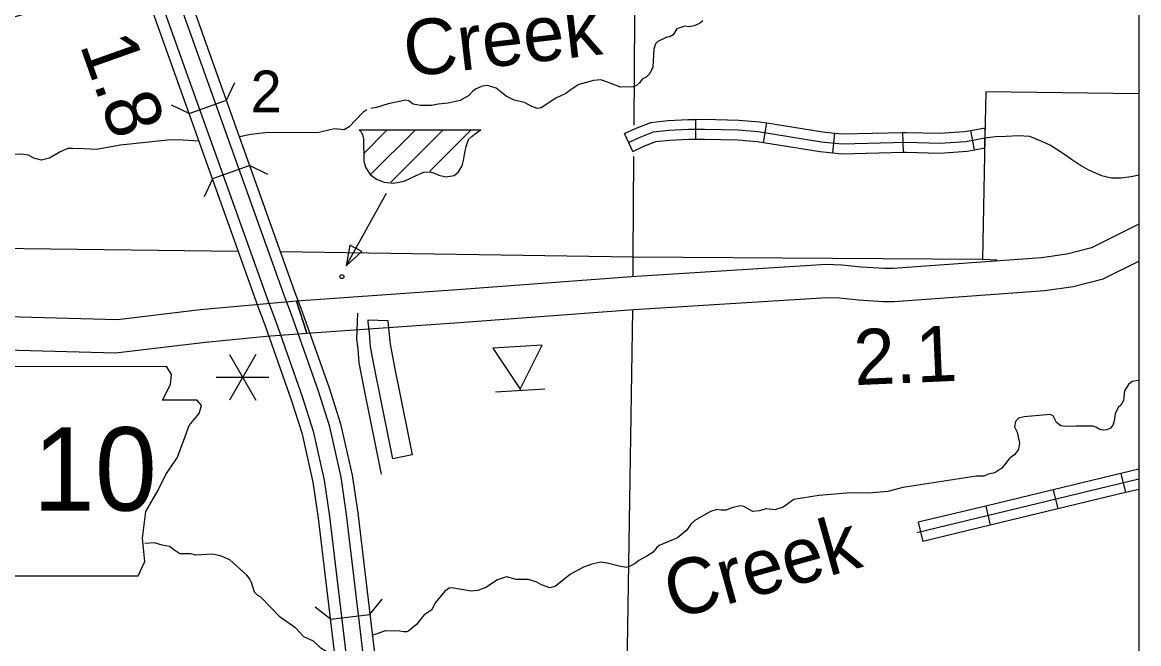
# Model space of a CAD drawing. Extents: x 1370567 to 1373900, y 377514 to 379648.
# Drawn here: x 1372783.2 to 1373025.5, y 377951.9 to 378086.8 of the extents above; entities that cross this region are included whole.
import ezdxf

# ---------------------------------------------------------------- set-up
doc = ezdxf.new("R2010")
doc.units = 0
doc.layers.add('Default', color=7, linetype='Continuous')
doc.layers.add('Survey Symbols', color=7, linetype='Continuous')

msp = doc.modelspace()

# ---------------------------------------------------------------- linework, layer by layer
at = {"layer": 'Default'}
for p, q in [((1372827.47, 378069.87), (1372829.31, 378073.74)), ((1372819.4, 378066.99), (1372827.47, 378069.87)), ((1372819.4, 378066.99), (1372815.53, 378068.82)), ((1372929.41, 378061.44), (1372929.38, 378065.72)), ((1372944.1, 378060.71), (1372944.78, 378064.94)), ((1372856.28, 378063.47), (1372882.68, 378063.47)), ((1372857.37, 378058.4), (1372862.34, 378063.37)), ((1372858.84, 378053.82), (1372868.37, 378063.34)), ((1372863.19, 378052.11), (1372874.48, 378063.39)), ((1372871.65, 378054.5), (1372880.48, 378063.33)), ((1372915.72, 378058.76), (1372913.89, 378062.63)), ((1372959.13, 378058.45), (1372959.58, 378062.72)), ((1372974.48, 378058.61), (1372974.37, 378062.89)), ((1372989.87, 378059.09), (1372989.08, 378063.31)), ((1372832.53, 378055.68), (1372824.46, 378052.8)), ((1372832.53, 378055.68), (1372836.41, 378053.84)), ((1372824.46, 378052.8), (1372822.62, 378048.93)), ((1372844.95, 378019.27), (1372842.68, 378026.27)), ((1372842.68, 378026.27), (1372844.95, 378019.27)), ((1372844.95, 378019.27), (1372842.68, 378026.27)), ((1372858.27, 378022.2), (1372862.55, 378022.02)), ((1372896.01, 378016.72), (1372885.32, 378016.04)), ((1372891.26, 378007.12), (1372896.01, 378016.72)), ((1372833.83, 378014.68), (1372828.11, 378004.79)), ((1372828.11, 378014.68), (1372833.83, 378004.79)), ((1372885.32, 378016.04), (1372891.26, 378007.12)), ((1372825.25, 378009.74), (1372836.68, 378009.74)), ((1372896.62, 378007.18), (1372885.93, 378006.5)), ((1372891.26, 378007.12), (1372891.27, 378006.84)), ((1372867.82, 377992.87), (1372863.62, 377992.02)), ((1373021.66, 377988.85), (1373022.66, 377984.68)), ((1373006.99, 377985.32), (1373008, 377981.15)), ((1372992.33, 377981.78), (1372993.33, 377977.62)), ((1372977.66, 377978.25), (1372978.66, 377974.08)), ((1372858.61, 377958.21), (1372861.26, 377961.58)), ((1372850.1, 377957.19), (1372846.73, 377959.84)), ((1372850.1, 377957.19), (1372858.61, 377958.21))]:
    msp.add_line(p, q, dxfattribs=at)
for points in [[(1372916.23, 378111.53), (1372915.93, 378064.44)], [(1372813.84, 378100.85), (1372816, 378102.03), (1372842.34, 378028.17), (1372843.95, 378023.97), (1372849.75, 378007.47), (1372852.25, 377999.64), (1372854.78, 377988.5), (1372855.98, 377980.29), (1372867.18, 377886.4)], [(1372808.32, 378098.05), (1372810.51, 378099.13), (1372836.58, 378026.05), (1372838.18, 378021.86), (1372843.92, 378005.52), (1372846.31, 377998.02), (1372848.73, 377987.38), (1372849.89, 377979.48), (1372861.08, 377885.68)], [(1372864.76, 377886.12), (1372853.57, 377979.97), (1372852.39, 377988.06), (1372849.9, 377999), (1372847.44, 378006.7), (1372841.66, 378023.13), (1372840.07, 378027.33), (1372813.84, 378100.85)], [(1372858.66, 377885.39), (1372847.48, 377979.16), (1372846.34, 377986.93), (1372843.97, 377997.38), (1372841.62, 378004.74), (1372835.9, 378021.02), (1372834.3, 378025.21), (1372808.32, 378098.05)], [(1372930.89, 378087.11), (1372930.18, 378086.54), (1372929.01, 378086)], [(1372929.01, 378086), (1372927.95, 378085.8), (1372926.98, 378085.98), (1372925.24, 378085.35), (1372924.5, 378084.06), (1372923.78, 378083.67), (1372923.07, 378083.55), (1372921.13, 378082.61), (1372920.64, 378082.13), (1372920.3, 378080.98), (1372920.07, 378077.07), (1372919.41, 378075.65), (1372918.61, 378074.88), (1372917.73, 378074.45), (1372917.13, 378073.65), (1372916.5, 378073.11), (1372915.79, 378072.82), (1372913.05, 378072.74), (1372910.25, 378073.77), (1372908.79, 378074.34), (1372907.2, 378074.2), (1372903.97, 378073.32), (1372902.51, 378072.35), (1372901.17, 378071.35), (1372899, 378070.32), (1372895.83, 378068.24), (1372894.97, 378068.07), (1372893.66, 378068.62), (1372892.18, 378069.42), (1372889.95, 378069.87), (1372888.21, 378070.76), (1372886.04, 378072.47), (1372884.16, 378073.07), (1372882.99, 378072.93), (1372881.59, 378072.31), (1372880.87, 378071.79), (1372880.1, 378070.94), (1372878.25, 378069.85), (1372875.59, 378069.26), (1372873.42, 378069.06), (1372871.99, 378068.74), (1372869.6, 378068.77), (1372868.05, 378069.06)], [(1372868.05, 378069.06), (1372867.06, 378069.72), (1372866.4, 378069.92), (1372862.57, 378069.09), (1372860.03, 378068.32), (1372858.83, 378068.1)], [(1373025.55, 378071.29), (1372992.35, 378071.71), (1372992.15, 378061.69), (1372991.63, 378035.35), (1372994.8, 378035.23)], [(1372857.95, 378067.76), (1372857.09, 378067.21), (1372854.09, 378064.1), (1372853.04, 378063.48), (1372850.95, 378063.68), (1372847.24, 378062.8), (1372836.45, 378062.89), (1372832.74, 378062.46), (1372830.31, 378061.91)], [(1372913.89, 378062.63), (1372916.45, 378063.83), (1372919.65, 378065.08), (1372923.31, 378065.51), (1372927.77, 378065.72), (1372929.38, 378065.72)], [(1372929.38, 378065.72), (1372931.31, 378065.74), (1372938.71, 378065.56), (1372943.19, 378065.2), (1372944.78, 378064.94)], [(1372944.78, 378064.94), (1372956.97, 378062.99), (1372959.58, 378062.72)], [(1372856.28, 378063.47), (1372856.66, 378063.06), (1372857.01, 378062.43), (1372857.25, 378061.48), (1372857.25, 378060.06), (1372857.29, 378058.21), (1372857.29, 378056.55), (1372857.76, 378055.17), (1372858.67, 378053.75), (1372860.09, 378052.73), (1372861.75, 378052.1), (1372863.76, 378051.9), (1372866.05, 378052.33), (1372868.69, 378053.52), (1372870.31, 378054.23), (1372871.69, 378054.34), (1372872.63, 378054.07), (1372873.58, 378053.59), (1372875.12, 378053.24), (1372876.89, 378053.55), (1372877.84, 378054.34), (1372878.63, 378055.65), (1372878.98, 378056.79), (1372879.18, 378058.13), (1372879.5, 378059.83), (1372880.05, 378061.36), (1372880.8, 378062.07), (1372881.74, 378062.82), (1372882.68, 378063.47)], [(1372914.81, 378060.69), (1372917.29, 378061.87), (1372920.17, 378062.99), (1372923.49, 378063.38), (1372927.83, 378063.57), (1372931.29, 378063.59), (1372938.59, 378063.42), (1372942.93, 378063.07), (1372956.69, 378060.86), (1372961.09, 378060.4), (1372975.11, 378060.76), (1372982.36, 378060.56), (1372988.01, 378060.93), (1372992.15, 378061.69)], [(1372959.58, 378062.72), (1372961.17, 378062.55), (1372974.37, 378062.89)], [(1372974.37, 378062.89), (1372975.11, 378062.91), (1372982.32, 378062.7), (1372987.74, 378063.06), (1372989.08, 378063.31)], [(1372989.08, 378063.31), (1372992.19, 378063.88)], [(1372989.87, 378059.09), (1372992.11, 378059.51), (1372992.19, 378063.88)], [(1372821.54, 378060.98), (1372816.89, 378061.28), (1372814.7, 378061.19), (1372804.45, 378060.09), (1372799.25, 378059.2), (1372796.51, 378059.32), (1372794.03, 378059.41), (1372793.06, 378059.38), (1372791.37, 378058.67), (1372789.06, 378057.3), (1372787.35, 378056.84), (1372785.63, 378057.3), (1372784.52, 378057.93), (1372782.92, 378058.16), (1372781.04, 378058.13), (1372776.75, 378058.91), (1372774.16, 378058.79), (1372771.07, 378058.17), (1372770.13, 378058.37), (1372768.06, 378057.78), (1372766.88, 378058)], [(1372915.72, 378058.76), (1372918.14, 378059.9), (1372920.69, 378060.89), (1372923.66, 378061.24), (1372927.88, 378061.43), (1372929.41, 378061.44)], [(1372929.41, 378061.44), (1372931.27, 378061.45), (1372938.48, 378061.28), (1372942.68, 378060.94), (1372944.1, 378060.71)], [(1372944.1, 378060.71), (1372956.41, 378058.74), (1372959.13, 378058.45)], [(1372992.15, 378061.69), (1372994.46, 378061.98), (1372996.78, 378062.09), (1372999.43, 378062.2), (1373001.83, 378062.06), (1373004.45, 378061), (1373006.4, 378060.14), (1373008.79, 378058.57), (1373010.96, 378057.06), (1373013.16, 378055.63), (1373014.67, 378054.77), (1373017.5, 378053.54), (1373019.64, 378053.03), (1373021.67, 378053), (1373023.95, 378053.31), (1373025.55, 378053.69)], [(1372915.89, 378057.66), (1372915.75, 378035.91), (1372915.72, 378031.59)], [(1372959.13, 378058.45), (1372961.01, 378058.26), (1372974.48, 378058.61)], [(1372974.48, 378058.61), (1372975.1, 378058.62), (1372982.4, 378058.41), (1372988.28, 378058.8), (1372989.87, 378059.09)], [(1372853.44, 378033.91), (1372862.21, 378049.71)], [(1373025.55, 378042.95), (1373015.33, 378037.81), (1373009.96, 378036.48), (1373004.42, 378035.69), (1372972.23, 378033.34), (1372970.33, 378033.34), (1372965.31, 378033.65), (1372961.09, 378034.08), (1372957.74, 378034.18), (1372915.45, 378031.54), (1372877.58, 378028.74), (1372842.68, 378026.27)], [(1372766, 378037.93), (1372830.05, 378037.14)], [(1372839.19, 378037.02), (1372915.75, 378035.91), (1372991.63, 378035.35)], [(1372844.95, 378019.27), (1372878.09, 378021.62), (1372915.93, 378024.42), (1372957.86, 378027.03), (1372960.62, 378026.95), (1372964.73, 378026.53), (1372970.11, 378026.2), (1372972.49, 378026.19), (1373005.18, 378028.59), (1373011.32, 378029.45), (1373017.83, 378031.08), (1373025.55, 378034.95)], [(1372842.68, 378026.27), (1372821.8, 378024.38), (1372803.85, 378022.21), (1372763.92, 378023.29), (1372687.69, 378024.58), (1372681.36, 378024.32), (1372671.63, 378023.6), (1372656.66, 378022.09), (1372638.12, 378019.67), (1372612.13, 378016.52)], [(1372861.13, 377988.68), (1372857.5, 378006.6), (1372856.29, 378012.9), (1372856.05, 378015.8), (1372855.81, 378018.1), (1372856.03, 378023.64)], [(1372915.63, 378024.33), (1372914.34, 377941.76)], [(1372860.63, 378006.8), (1372859.99, 378009.94), (1372858.75, 378016.36), (1372858.51, 378019.36), (1372858.25, 378021.79), (1372858.27, 378022.2)], [(1372862.55, 378022.02), (1372862.54, 378021.93), (1372862.77, 378019.76), (1372863.01, 378016.95), (1372864.19, 378010.77), (1372864.83, 378007.65)], [(1372593.93, 378006.74), (1372613.05, 378009.44), (1372639.02, 378012.59), (1372657.48, 378014.99), (1372672.25, 378016.49), (1372681.77, 378017.19), (1372687.77, 378017.43), (1372763.76, 378016.15), (1372803.42, 378015.07), (1372822.93, 378017.32), (1372836.2, 378018.65), (1372844.95, 378019.27)], [(1373025.55, 378009.05), (1373025.42, 378009.06), (1373024.11, 378008.78), (1373023.34, 378008.15), (1373022.48, 378006.78), (1373022.22, 378004.7), (1373021.68, 378003.7), (1373021.11, 378003.16), (1373020.42, 378001.79), (1373020.22, 378000.25), (1373019.91, 377999.36), (1373019.45, 377998.68), (1373018.6, 377998.33), (1373017.82, 377998.22), (1373017.14, 377998.39), (1373016.26, 377998.91), (1373015.63, 377999.11), (1373011.94, 377999.14), (1373009.57, 377999.05), (1373008.63, 377999.2), (1373007.72, 377999.88), (1373006.95, 378001.37), (1373006.32, 378001.63), (1373000.67, 378001.17), (1372999.47, 378000.83), (1372998.84, 378000.15), (1372998.58, 377999), (1372999.15, 377997.81), (1372999.7, 377995.41), (1372999.47, 377994.12), (1372998.64, 377992.95), (1372998.18, 377992.61)], [(1372863.62, 377992.02), (1372860.63, 378006.8)], [(1372864.83, 378007.65), (1372867.82, 377992.87)], [(1372998.18, 377992.61), (1372997.41, 377992.04), (1372995.81, 377990.01), (1372994.3, 377988.96), (1372992.87, 377988.67), (1372991.93, 377988.28), (1372990.3, 377988.28), (1372974.31, 377985.8), (1372971.06, 377984.92), (1372966.92, 377984.55), (1372962.98, 377984.61), (1372956.13, 377984.08), (1372950.7, 377983.2), (1372948.39, 377981.54), (1372946.54, 377980.94), (1372944.77, 377981.17), (1372943.17, 377980.72), (1372941.77, 377980.58), (1372939.8, 377981.66), (1372939.03, 377981.8), (1372937.23, 377981.38), (1372935.97, 377980.89), (1372934.83, 377980.89), (1372933.95, 377981.04), (1372932.58, 377980.55), (1372929.15, 377978.61), (1372928.32, 377977.82), (1372927.46, 377976.53), (1372925.44, 377974.88), (1372921.47, 377973.23), (1372920.9, 377972.8), (1372920.1, 377971.77), (1372918.78, 377970.91), (1372917.01, 377969.97), (1372916.21, 377969.29), (1372914.82, 377968.58), (1372914.27, 377968.41), (1372912.73, 377968.72), (1372910.16, 377969.38), (1372908.76, 377969.55)], [(1373025.55, 377989.79), (1373021.66, 377988.85)], [(1373025.55, 377987.58), (1372977.39, 377975.98)], [(1373021.66, 377988.85), (1373006.99, 377985.32)], [(1373006.99, 377985.32), (1372992.33, 377981.78)], [(1373025.55, 377985.38), (1373022.66, 377984.68)], [(1373022.66, 377984.68), (1373008, 377981.15)], [(1372992.33, 377981.78), (1372977.66, 377978.25)], [(1373008, 377981.15), (1372993.33, 377977.62)], [(1372993.33, 377977.62), (1372978.66, 377974.08)], [(1372850.99, 377949.29), (1372850.54, 377949.29), (1372847.98, 377950.9), (1372846.35, 377952.41), (1372844.3, 377953.35), (1372842.53, 377955.27), (1372839.13, 377957.64), (1372834.96, 377962.01), (1372834.28, 377962.38), (1372833.54, 377963.07), (1372832.91, 377965.18), (1372832.48, 377966.07), (1372831.94, 377966.75), (1372828.23, 377970.07), (1372826.2, 377970.95), (1372824.46, 377971.35), (1372820.86, 377971.07), (1372819.75, 377971.41), (1372817.35, 377971.41), (1372816.24, 377972.13), (1372815.13, 377973.01), (1372813.55, 377973.3), (1372811.84, 377973.79), (1372809.77, 377973.63)], [(1372908.76, 377969.55), (1372906.85, 377969.15), (1372905.02, 377968.47), (1372902.2, 377966.99), (1372898.88, 377964.28), (1372897.66, 377964.02), (1372895.86, 377964.65), (1372894.89, 377965.25), (1372893.09, 377965.79), (1372890.41, 377965.85), (1372888.29, 377966.4), (1372886.35, 377965.77), (1372883.81, 377964.09), (1372882.07, 377963.46), (1372880.58, 377963.29), (1372876.45, 377963.98), (1372875.87, 377963.92), (1372874.93, 377963.32), (1372872.85, 377960.81), (1372871.99, 377959.19), (1372870.42, 377958.16), (1372868.73, 377956.02), (1372867.08, 377954.65), (1372866.65, 377954.48), (1372865.91, 377954.45), (1372865.11, 377954.62), (1372862, 377954.66), (1372859.28, 377953.77), (1372859.13, 377953.61)]]:
    msp.add_lwpolyline(points, dxfattribs=at)
for points in [[(1372856.84, 378037.03), (1372854.29, 378038.44), (1372853.44, 378033.91)], [(1372771.08, 378012.04), (1372773.26, 377997.53), (1372772.29, 377975.54), (1372774.22, 377974.33), (1372777.85, 377974.33), (1372777.85, 377966.6), (1372808.3, 377966.6), (1372809.75, 377969.74), (1372809.27, 377974.82), (1372809.99, 377980.62), (1372812.65, 377985.21), (1372814.34, 377988.59), (1372816.76, 377992.22), (1372818.21, 377996.08), (1372819.42, 377999.23), (1372821.59, 378001.88), (1372822.08, 378003.58), (1372821.11, 378004.79), (1372813.62, 378004.79), (1372815.31, 378008.17), (1372815.55, 378010.34), (1372814.55, 378012.01)]]:
    msp.add_lwpolyline(points, close=True, dxfattribs=at)
msp.add_circle((1372852.54, 378031.58), 0.429, dxfattribs=at)
msp.add_arc((1372741.09, 378237.31), 154.64, 228.844, 356.8229, dxfattribs=at)
at = {"layer": 'Survey Symbols'}
msp.add_lwpolyline([(1371518.13, 378743.2), (1373025.55, 378743.2), (1373025.55, 377817.56), (1371518.13, 377817.56)], close=True, dxfattribs=at)
msp.add_lwpolyline([(1371518.13, 378743.2), (1373025.55, 378743.2), (1373025.55, 377817.56), (1371518.13, 377817.56)], close=True, dxfattribs=at)
msp.add_lwpolyline([(1371518.13, 378743.2), (1373025.55, 378743.2), (1373025.55, 377817.56), (1371518.13, 377817.56)], close=True, dxfattribs=at)

# ---------------------------------------------------------------- texts
at = {"layer": 'Default'}
for s, rotation, p in [('Creek', 6.6441, (1372866.64, 378074.9)), ('1.8', 289.5438, (1372795.56, 378081.92)), ('2.1', 2.4636, (1372963.93, 378008.01)), ('Creek', 15.5527, (1372924.53, 377957.11))]:
    msp.add_text(s, height=12.069, rotation=rotation, dxfattribs=at).set_placement(p)
for s, height, p in [('2', 9.05, (1372832.74, 378067.27)), ('10', 18.103, (1372785.45, 377980.77))]:
    msp.add_text(s, height=height, dxfattribs=at).set_placement(p)

doc.saveas('drawing.dxf')
